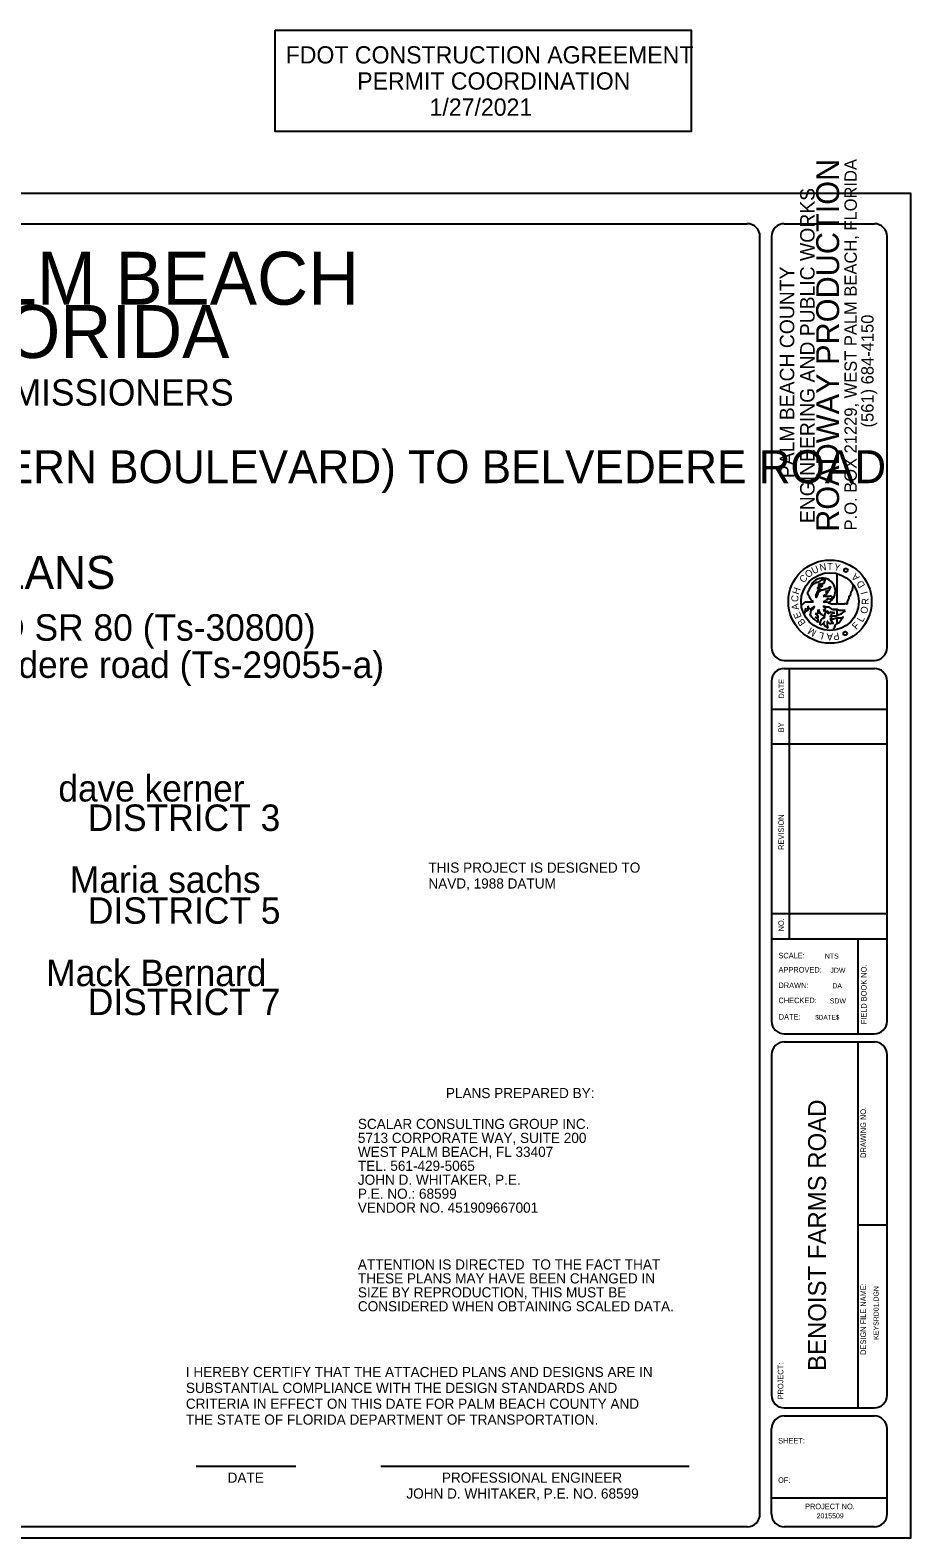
# Model space of a CAD drawing. Extents: x 801329 to 1085229, y 842463 to 1044570.
# Drawn here: x 967224 to 1085229, y 842463 to 1044570 of the extents above; entities that cross this region are included whole.
import ezdxf

# ---------------------------------------------------------------- set-up
doc = ezdxf.new("R2010")
doc.units = 0
for name, color, linetype in [('Default', 7, 'Continuous'), ('PlotBorder_dp', 7, 'Continuous'), ('TextLabel', 7, 'Continuous')]:
    doc.layers.add(name, color=color, linetype=linetype)

msp = doc.modelspace()

# ---------------------------------------------------------------- linework, layer by layer
at = {"layer": 'Default'}
for p, q in [((813867, 1018625), (1063315, 1018625)), ((1068269, 1018625), (1080341, 1018625)), ((1065015, 845650), (1065015, 1016925)), ((1066569, 1016925), (1066569, 961794)), ((1082041, 961794), (1082041, 1016925)), ((1071961, 970146), (1071888, 969999)), ((1071961, 970146), (1072107, 970293)), ((1072107, 970293), (1072181, 970293)), ((1072181, 970293), (1072328, 970440)), ((1072328, 970440), (1072474, 970440)), ((1072474, 970440), (1072547, 970586)), ((1072547, 970586), (1072915, 970586)), ((1072988, 970293), (1072842, 970146)), ((1072842, 970146), (1073355, 970146)), ((1072915, 970586), (1073282, 970879)), ((1073061, 970293), (1072988, 970293)), ((1073061, 970293), (1073282, 970293)), ((1073282, 970879), (1073648, 971026)), ((1073574, 970440), (1073282, 970293)), ((1073648, 970586), (1073574, 970440)), ((1073648, 971026), (1073721, 970879)), ((1073721, 970879), (1073648, 970586)), ((1073648, 970586), (1073648, 970586)), ((1075335, 971613), (1075335, 967652)), ((1077463, 969706), (1077535, 970293)), ((1071448, 968972), (1071448, 969266)), ((1071448, 969266), (1071521, 969266)), ((1071521, 968825), (1071448, 968972)), ((1071521, 969413), (1071594, 969559)), ((1071521, 969266), (1071521, 969413)), ((1071667, 968679), (1071521, 968825)), ((1071594, 969559), (1071667, 969559)), ((1071667, 969706), (1071814, 969999)), ((1071667, 969559), (1071667, 969706)), ((1071667, 968532), (1071667, 968679)), ((1071814, 968239), (1071667, 968532)), ((1071814, 969999), (1071888, 969999)), ((1071814, 969999), (1071814, 969999)), ((1071888, 968239), (1071814, 968239)), ((1071961, 968092), (1071888, 968239)), ((1072621, 968972), (1072547, 968972)), ((1072547, 968972), (1072547, 968825)), ((1072547, 968825), (1072547, 968679)), ((1072547, 968825), (1072547, 968825)), ((1072547, 968532), (1072694, 968825)), ((1072547, 968679), (1072547, 968532)), ((1072621, 968972), (1072694, 969266)), ((1072768, 969266), (1072694, 969266)), ((1072768, 968972), (1072694, 968825)), ((1072842, 969853), (1072768, 969853)), ((1072768, 969853), (1072768, 969706)), ((1072768, 969706), (1072988, 969706)), ((1072842, 969559), (1072768, 969266)), ((1072768, 968972), (1072768, 969119)), ((1072988, 969999), (1072842, 969853)), ((1072988, 969559), (1072842, 969559)), ((1073061, 969413), (1072915, 969266)), ((1073282, 969999), (1072988, 969999)), ((1073282, 969559), (1073061, 969413)), ((1073282, 969999), (1073282, 969999)), ((1073282, 969559), (1073501, 969559)), ((1073648, 969559), (1073501, 969559)), ((1073721, 968825), (1073501, 968679)), ((1073501, 968679), (1073501, 968679)), ((1073501, 968679), (1073574, 968679)), ((1073501, 968679), (1073501, 968679)), ((1073721, 968679), (1073574, 968679)), ((1073648, 969559), (1073795, 969706)), ((1073941, 968972), (1073721, 968825)), ((1073721, 968679), (1074088, 968679)), ((1073795, 969706), (1074015, 969706)), ((1074235, 969413), (1073795, 969266)), ((1073795, 969266), (1074162, 969266)), ((1073941, 968239), (1073867, 968092)), ((1074162, 969266), (1073941, 968972)), ((1074088, 968239), (1073941, 968239)), ((1074015, 969706), (1074308, 969853)), ((1074381, 968239), (1074015, 968386)), ((1074015, 968386), (1074088, 968239)), ((1074088, 968679), (1074308, 968679)), ((1074308, 969559), (1074235, 969413)), ((1074308, 969853), (1074528, 969999)), ((1074381, 969706), (1074308, 969559)), ((1074308, 968679), (1074381, 968679)), ((1074528, 969999), (1074381, 969706)), ((1074602, 968679), (1074381, 968679)), ((1074602, 968386), (1074381, 968239)), ((1074602, 968679), (1074749, 968532)), ((1074895, 968532), (1074602, 968386)), ((1074749, 968532), (1074895, 968532)), ((1076803, 968092), (1076949, 968386)), ((1076949, 968679), (1077169, 968825)), ((1076949, 968532), (1076949, 968679)), ((1076949, 968386), (1076949, 968532)), ((1077169, 968972), (1077242, 969266)), ((1077169, 968825), (1077169, 968972)), ((1077242, 969266), (1077389, 969413)), ((1077389, 969413), (1077463, 969706)), ((1070568, 967505), (1070641, 967505)), ((1070641, 967505), (1070713, 967652)), ((1070713, 967652), (1070787, 967652)), ((1070787, 967652), (1070934, 967799)), ((1070934, 967799), (1071081, 967946)), ((1071007, 966479), (1070934, 966332)), ((1071081, 966919), (1071007, 966626)), ((1071007, 966626), (1071007, 966479)), ((1071081, 967946), (1071227, 967946)), ((1071153, 967065), (1071081, 966919)), ((1071153, 966919), (1071153, 967065)), ((1071153, 966626), (1071153, 966919)), ((1071448, 966772), (1071153, 966626)), ((1071153, 966626), (1071153, 966626)), ((1071153, 966626), (1071153, 966626)), ((1071227, 967946), (1071448, 967946)), ((1071448, 967946), (1071448, 967946)), ((1071448, 967946), (1071667, 967946)), ((1071521, 967211), (1071448, 967358)), ((1071448, 967358), (1071448, 967211)), ((1071448, 967211), (1071448, 967211)), ((1071448, 967211), (1071448, 966919)), ((1071448, 966919), (1071448, 966772)), ((1071667, 966919), (1071521, 967211)), ((1071667, 967946), (1071888, 967946)), ((1072328, 967358), (1071667, 966919)), ((1071741, 966332), (1071814, 966479)), ((1071814, 966038), (1071741, 966332)), ((1071741, 966332), (1071741, 966332)), ((1071814, 966626), (1071961, 966919)), ((1071814, 966479), (1071814, 966626)), ((1071888, 967946), (1072181, 967946)), ((1072181, 967946), (1071961, 968092)), ((1071961, 966919), (1072035, 966919)), ((1072035, 966919), (1072254, 967211)), ((1072254, 967211), (1072328, 967358)), ((1072768, 966332), (1072401, 966332)), ((1072401, 966332), (1072768, 966038)), ((1072768, 966772), (1072842, 966919)), ((1072768, 966772), (1072768, 966626)), ((1072768, 966626), (1072768, 966479)), ((1072768, 966479), (1072768, 966332)), ((1072768, 966332), (1072768, 966332)), ((1072915, 966772), (1072842, 966919)), ((1072842, 966919), (1072915, 966772)), ((1073061, 966479), (1072915, 966772)), ((1073135, 966332), (1073061, 966479)), ((1073355, 966185), (1073135, 966332)), ((1073501, 966038), (1073355, 966185)), ((1073574, 967946), (1073501, 967946)), ((1073574, 967946), (1073501, 967946)), ((1073501, 967946), (1073721, 967946)), ((1073941, 967211), (1073501, 967358)), ((1073501, 967358), (1073648, 967211)), ((1073648, 967211), (1073501, 967358)), ((1073795, 966919), (1073501, 966772)), ((1073501, 966772), (1074162, 966626)), ((1073574, 967946), (1073795, 968092)), ((1073721, 967065), (1073648, 967211)), ((1073721, 967946), (1073941, 967946)), ((1073721, 967065), (1073795, 966919)), ((1073721, 967065), (1073795, 966919)), ((1073867, 968092), (1073795, 968092)), ((1074308, 967211), (1073941, 967211)), ((1074162, 966626), (1074162, 966479)), ((1074162, 966332), (1074162, 966479)), ((1074162, 966332), (1074308, 966479)), ((1074162, 966332), (1074162, 966332)), ((1074162, 966332), (1074162, 966332)), ((1074749, 966919), (1074308, 967211)), ((1074381, 966479), (1074308, 966479)), ((1074381, 966479), (1074602, 966626)), ((1074602, 966185), (1074455, 966038)), ((1074528, 967652), (1075041, 967652)), ((1074602, 966626), (1074749, 966479)), ((1074675, 966332), (1074602, 966332)), ((1074602, 966185), (1074602, 966332)), ((1074821, 966479), (1074675, 966332)), ((1074749, 966919), (1075115, 966919)), ((1075115, 966919), (1074749, 966919)), ((1074749, 966479), (1074895, 966479)), ((1074821, 966479), (1075041, 966479)), ((1075041, 966479), (1074821, 966479)), ((1075041, 966479), (1074895, 966479)), ((1074895, 966479), (1075041, 966479)), ((1075041, 967652), (1075335, 967652)), ((1075335, 966919), (1075115, 966919)), ((1075482, 967652), (1075335, 967652)), ((1075629, 966772), (1075335, 966919)), ((1075335, 966919), (1075335, 966038)), ((1075556, 966185), (1075335, 966038)), ((1075482, 967652), (1075995, 967652)), ((1075556, 966185), (1075849, 966332)), ((1075995, 966772), (1075629, 966772)), ((1075849, 966332), (1075922, 966332)), ((1075922, 966332), (1075849, 966332)), ((1075922, 966332), (1076069, 966479)), ((1075995, 967652), (1076362, 967652)), ((1076435, 966772), (1075995, 966772)), ((1076069, 966479), (1076362, 966626)), ((1076582, 967652), (1076362, 967652)), ((1076362, 966626), (1076435, 966772)), ((1076582, 967652), (1076655, 967652)), ((1076655, 967652), (1076729, 967652)), ((1076729, 967946), (1076803, 968092)), ((1076729, 967652), (1076729, 967946)), ((1071888, 966038), (1071814, 966038)), ((1071961, 965891), (1071888, 966038)), ((1072107, 965745), (1071961, 965891)), ((1072254, 965598), (1072107, 965745)), ((1072768, 965159), (1072254, 965598)), ((1072768, 965745), (1072401, 965891)), ((1072401, 965891), (1072768, 965598)), ((1072768, 966038), (1072768, 965745)), ((1072768, 965598), (1072768, 965159)), ((1073061, 965305), (1073135, 965305)), ((1073061, 965305), (1073061, 965159)), ((1073061, 965011), (1073061, 965159)), ((1073061, 964865), (1073061, 965011)), ((1073135, 964865), (1073061, 964865)), ((1073061, 964865), (1073061, 964865)), ((1073135, 965305), (1073282, 965598)), ((1073282, 964865), (1073135, 964865)), ((1073282, 965598), (1073501, 965745)), ((1073282, 965598), (1073282, 965598)), ((1073721, 965305), (1073282, 964865)), ((1073574, 966038), (1073501, 966038)), ((1073501, 965745), (1073721, 965891)), ((1073721, 965891), (1073501, 965745)), ((1073721, 965891), (1073574, 966038)), ((1073574, 965011), (1073574, 965159)), ((1073648, 964865), (1073574, 965011)), ((1073721, 964718), (1073648, 964865)), ((1073795, 964571), (1073721, 964718)), ((1073867, 964571), (1073795, 964571)), ((1074015, 964571), (1073867, 964571)), ((1074088, 965305), (1074015, 965305)), ((1074015, 965305), (1074015, 965305)), ((1074015, 965305), (1074015, 965159)), ((1074015, 965159), (1074015, 965011)), ((1074015, 965011), (1074015, 964865)), ((1074015, 964865), (1074015, 964718)), ((1074015, 964718), (1074088, 964425)), ((1074015, 964571), (1074015, 964425)), ((1074088, 964425), (1074015, 964425)), ((1074162, 965159), (1074088, 965305)), ((1074308, 965011), (1074162, 965159)), ((1074381, 965011), (1074308, 965011)), ((1074821, 965598), (1074381, 965598)), ((1074455, 965598), (1074381, 965598)), ((1074381, 965011), (1074528, 965011)), ((1074455, 966038), (1074455, 966038)), ((1074455, 966038), (1074455, 965891)), ((1074455, 965891), (1074455, 966038)), ((1074455, 965891), (1074528, 965891)), ((1074749, 965159), (1074455, 965598)), ((1074528, 965891), (1074602, 965891)), ((1074602, 965011), (1074528, 965011)), ((1074602, 965891), (1074821, 966038)), ((1074749, 965011), (1074602, 965011)), ((1074749, 965159), (1074821, 965011)), ((1074895, 965011), (1074749, 965011)), ((1074821, 966038), (1075335, 966038)), ((1075335, 965745), (1074821, 965598)), ((1074895, 964425), (1075041, 964571)), ((1074895, 964278), (1074895, 964425)), ((1074895, 964278), (1074895, 964278)), ((1074895, 964131), (1074895, 964278)), ((1075041, 964571), (1075115, 964865)), ((1075115, 964865), (1075335, 965011)), ((1075922, 965745), (1075335, 965745)), ((1075335, 965745), (1075335, 965011)), ((1075335, 965011), (1075629, 965159)), ((1075629, 965159), (1075922, 965598)), ((1075922, 965598), (1076215, 965891)), ((1076141, 965891), (1075922, 965745)), ((1076215, 965891), (1076141, 965891)), ((1068269, 960094), (1080341, 960094)), ((1068269, 959006), (1080341, 959006)), ((1068904, 959006), (1068904, 922753)), ((1066569, 957306), (1066569, 911729)), ((1082041, 911729), (1082041, 957306)), ((1066569, 953559), (1082042, 953559)), ((1066569, 948890), (1082042, 948890)), ((1066569, 926147), (1082042, 926147)), ((1066533, 922753), (1082083, 922753)), ((1078123, 922753), (1078123, 910136)), ((1068269, 910029), (1080341, 910029)), ((1068269, 908941), (1080341, 908941)), ((1078123, 908941), (1078123, 859888)), ((1066569, 907241), (1066569, 861589)), ((1082041, 861589), (1082041, 907241)), ((1078123, 884415), (1082041, 884415)), ((1068269, 859889), (1080341, 859889)), ((1066570, 845650), (1066570, 857100)), ((1068270, 858800), (1080341, 858800)), ((1082041, 845650), (1082041, 857100)), ((989461, 852087), (1002832, 852087)), ((1014202, 852087), (1055517, 852087)), ((1082083, 847781), (1066533, 847781)), ((1063315, 843950), (813867, 843950)), ((1080341, 843950), (1068270, 843950))]:
    msp.add_line(p, q, dxfattribs=at)
msp.add_lwpolyline([(1000046, 1044570), (1055792, 1044570), (1055792, 1030991), (1000046, 1030991)], close=True, dxfattribs=at)
for points in [[(1072915, 969266), (1072842, 969266), (1072768, 969119), (1072768, 968972), (1072694, 968825), (1072547, 968532), (1072547, 968679), (1072547, 968825), (1072547, 968825), (1072547, 968972), (1072621, 968972), (1072694, 969266), (1072768, 969266), (1072842, 969559), (1072988, 969559), (1072988, 969559), (1072988, 969706), (1072768, 969706), (1072768, 969853), (1072842, 969853), (1072988, 969999), (1073282, 969999), (1073282, 969999), (1073355, 970146), (1072842, 970146), (1072988, 970293), (1073061, 970293), (1073282, 970293), (1073574, 970440), (1073648, 970586), (1073648, 970586), (1073721, 970879), (1073648, 971026)], [(1073648, 971026), (1073721, 970879), (1073648, 970586), (1073648, 970586), (1073574, 970440), (1073282, 970293), (1073061, 970293), (1072988, 970293), (1072842, 970146), (1073355, 970146), (1073282, 969999), (1073282, 969999), (1072988, 969999), (1072842, 969853), (1072768, 969853), (1072768, 969706), (1072988, 969706), (1072988, 969559), (1072988, 969559), (1072842, 969559), (1072768, 969266), (1072694, 969266), (1072621, 968972), (1072547, 968972), (1072547, 968825), (1072547, 968825), (1072547, 968679), (1072547, 968532), (1072694, 968825), (1072768, 968972), (1072768, 969119), (1072842, 969266), (1072915, 969266)]]:
    msp.add_lwpolyline(points, dxfattribs=at)
for centre, radius in [((1074396, 967961), 5574), ((1076524, 972173), 249), ((1074396, 967961), 3876), ((1076434, 963695), 249)]:
    msp.add_circle(centre, radius, dxfattribs=at)
for centre, radius, start, end in [((1063315, 1016925), 1700, 0, 90), ((1068269, 1016925), 1700, 90, 180), ((1080341, 1016925), 1700, 0, 90), ((1073391, 969374), 1727, 296.39658, 159.2296), ((1074284, 966029), 652, 120.85608, 187.16512), ((1076638, 974288), 6914, 246.84631, 252.0416), ((1068269, 961794), 1700, 180, 270), ((1080341, 961794), 1700, 270, 360), ((1068269, 957306), 1700, 90, 180), ((1080341, 957306), 1700, 0, 90), ((1068269, 911729), 1700, 180, 270), ((1080341, 911729), 1700, 270, 360), ((1068269, 907241), 1700, 90, 180), ((1080341, 907241), 1700, 0, 90), ((1068269, 861589), 1700, 180, 270), ((1080341, 861589), 1700, 270, 360), ((1068270, 857100), 1700, 90, 180), ((1080341, 857100), 1700, 0, 90), ((1063315, 845650), 1700, 270, 360), ((1068270, 845650), 1700, 180, 270), ((1080341, 845650), 1700, 270, 360)]:
    msp.add_arc(centre, radius, start, end, dxfattribs=at)
msp.add_ellipse((1074260, 966028), major_axis=(16, 652), ratio=0.9613992, start_param=0.21389, end_param=1.7191647, dxfattribs=at)
at = {"layer": 'PlotBorder_dp'}
msp.add_lwpolyline([(801329, 842463), (1085229, 842463), (1085229, 1022663), (801329, 1022663)], close=True, dxfattribs=at)

# ---------------------------------------------------------------- texts
at = {"layer": 'Default'}
for s, height, p in [('FDOT CONSTRUCTION AGREEMENT', 2312.85, (1001458, 1040102)), ('PERMIT COORDINATION', 2312.85, (1011048, 1036600)), ('1/27/2021', 2312.8, (1020742, 1033097)), ('SIGNALIZATION PLANS', 4419.99, (912618, 969676)), ('THIS PROJECT IS DESIGNED TO', 1360, (1020586, 931627)), ('NAVD, 1988 DATUM', 1360, (1020586, 929502)), ('SCALE:', 742, (1067488, 920146)), ('  NTS  ', 674, (1073190, 920110)), ('APPROVED:', 742, (1067500, 918247)), ('JDW', 674, (1074450, 918211)), ('DRAWN:', 742, (1067491, 916162)), ('DA', 674, (1074710, 916126)), ('CHECKED:', 742, (1067489, 914138)), ('SDW', 674, (1074371, 914102)), ('DATE:', 742, (1067532, 911929)), ('$DATE$', 619.5, (1072423, 911938)), ('PLANS PREPARED BY:', 1360, (1022932, 901408)), ('SCALAR CONSULTING GROUP INC.', 1360, (1011136, 897268)), ('5713 CORPORATE WAY, SUITE 200', 1360, (1011136, 895398)), ('WEST PALM BEACH, FL 33407', 1360, (1011136, 893528)), ('TEL. 561-429-5065', 1360, (1011136, 891658)), ('JOHN D. WHITAKER, P.E.', 1360, (1011136, 889788)), ('P.E. NO.: 68599', 1360, (1011136, 887918)), ('VENDOR NO. 451909667001', 1360, (1011136, 886048)), ('ATTENTION IS DIRECTED  TO THE FACT THAT', 1360, (1011136, 878435)), ('THESE PLANS MAY HAVE BEEN CHANGED IN', 1360, (1011136, 876565)), ('SIZE BY REPRODUCTION, THIS MUST BE', 1360, (1011136, 874695)), ('CONSIDERED WHEN OBTAINING SCALED DATA.', 1360, (1011136, 872825)), ('I HEREBY CERTIFY THAT THE ATTACHED PLANS AND DESIGNS ARE IN', 1360, (988091, 864011)), ('SUBSTANTIAL COMPLIANCE WITH THE DESIGN STANDARDS AND', 1360, (988091, 861886)), ('CRITERIA IN EFFECT ON THIS DATE FOR PALM BEACH COUNTY AND', 1360, (988091, 859761)), ('THE STATE OF FLORIDA DEPARTMENT OF TRANSPORTATION.', 1360, (988091, 857636)), ('SHEET:', 742, (1067444, 855115)), ('DATE', 1360, (993681, 849853)), ('PROFESSIONAL ENGINEER', 1360, (1022396, 849853)), ('JOHN D. WHITAKER, P.E. NO. 68599', 1360, (1017637, 847728)), ('OF:', 742, (1067444, 849834)), ('PROJECT NO.', 742.02, (1071054, 846300)), ('2015509', 674, (1072611, 845075))]:
    msp.add_text(s, height=height, dxfattribs=at).set_placement(p)
for s, height, rotation, p in [('ROADWAY PRODUCTION', 3073.81, 90, (1075619, 977315)), ('P.O. BOX 21229, WEST PALM BEACH, FLORIDA', 1653.96, 90, (1077991, 977511)), ('ENGINEERING AND PUBLIC WORKS', 1938.28, 90, (1072332, 978484)), ('PALM BEACH COUNTY', 1937.7, 90, (1069609, 984516)), ('(561) 684-4150', 1653.88, 90, (1080237, 991310)), ('O', 937, 36.82254, (1071455, 971078)), ('U', 937, 24.41588, (1072179, 971631)), ('N', 937, 11.04807, (1073089, 972042)), ('T', 937, 359.30925, (1074015, 972223)), ('Y', 937, 347.6879, (1074864, 972216)), ('C', 937, 49.28794, (1070879, 970403)), ('A', 937, 134.36794, (1078434, 971259)), ('D', 937, 119.86794, (1079141, 970125)), ('C', 937, 85.05948, (1070116, 967886)), ('H', 937, 71.25437, (1070197, 968836)), ('I', 937, 105.36794, (1079470, 969090)), ('R', 937, 90.86794, (1079595, 967539)), ('A', 937, 97.8515, (1070241, 966919)), ('E', 937, 112.64193, (1070634, 965922)), ('O', 937, 76.36794, (1079327, 966263)), ('B', 937, 125.61086, (1071195, 965119)), ('M', 937, 148.75881, (1072690, 964016)), ('F', 937, 47.36794, (1077932, 964136)), ('L', 937, 61.86794, (1078772, 965134)), ('L', 937, 164.5648, (1073676, 963742)), ('A', 937, 179.13874, (1074797, 963698)), ('P', 937, 189.79732, (1075561, 963842)), ('DATE', 742, 90, (1068249, 954959)), ('BY', 742, 90, (1068217, 950445)), ('REVISION', 742, 90, (1068217, 934696)), ('NO.', 742, 90, (1068218, 923763)), ('FIELD BOOK NO.', 742.02, 90, (1079295, 911310)), ('BENOIST FARMS ROAD', 2400, 90, (1073862, 864839)), ('DRAWING NO.', 742.02, 90, (1079222, 893403)), ('DESIGN FILE NAME:', 742.05, 90, (1079222, 866999)), ('KEYSRD01.DGN', 674.05, 90, (1080906, 869016)), ('PROJECT:', 742, 90, (1068145, 861024))]:
    msp.add_text(s, height=height, rotation=rotation, dxfattribs=at).set_placement(p)
at = {"layer": 'TextLabel'}
for s, height, p in [('COUNTY OF PALM BEACH', 7090.68, (891724, 1007768)), ('STATE OF FLORIDA', 7090.68, (903829, 1000628)), ('BOARD OF COUNTY COMMISSIONERS', 3544.49, (906281, 994236)), ('BENOIST FARMS ROAD - SR 80 (SOUTHERN BOULEVARD) TO BELVEDERE ROAD', 4419.99, (850713, 983842)), ('BENOIST FARMS ROAD AND SR 80 (Ts-30800)', 3544.49, (901443, 962727)), ('BENOIST FARMS ROAD AND belvedere road (Ts-29055-a)', 3544.49, (887950, 957738)), ('Mack Bernard', 3544.49, (969372, 916417))]:
    msp.add_text(s, height=height, dxfattribs=at).set_placement(p)
for s, height, p in [('dave kerner', 3531.23, (971005, 941169)), ('DISTRICT 3', 3544.7, (974928, 937225)), ('Maria sachs', 3544.7, (972548, 928929)), ('DISTRICT 5', 3544.3, (974961, 924781)), ('DISTRICT 7', 3544.7, (974949, 912541))]:
    msp.add_text(s, height=height, rotation=360, dxfattribs=at).set_placement(p)

doc.saveas('drawing.dxf')
